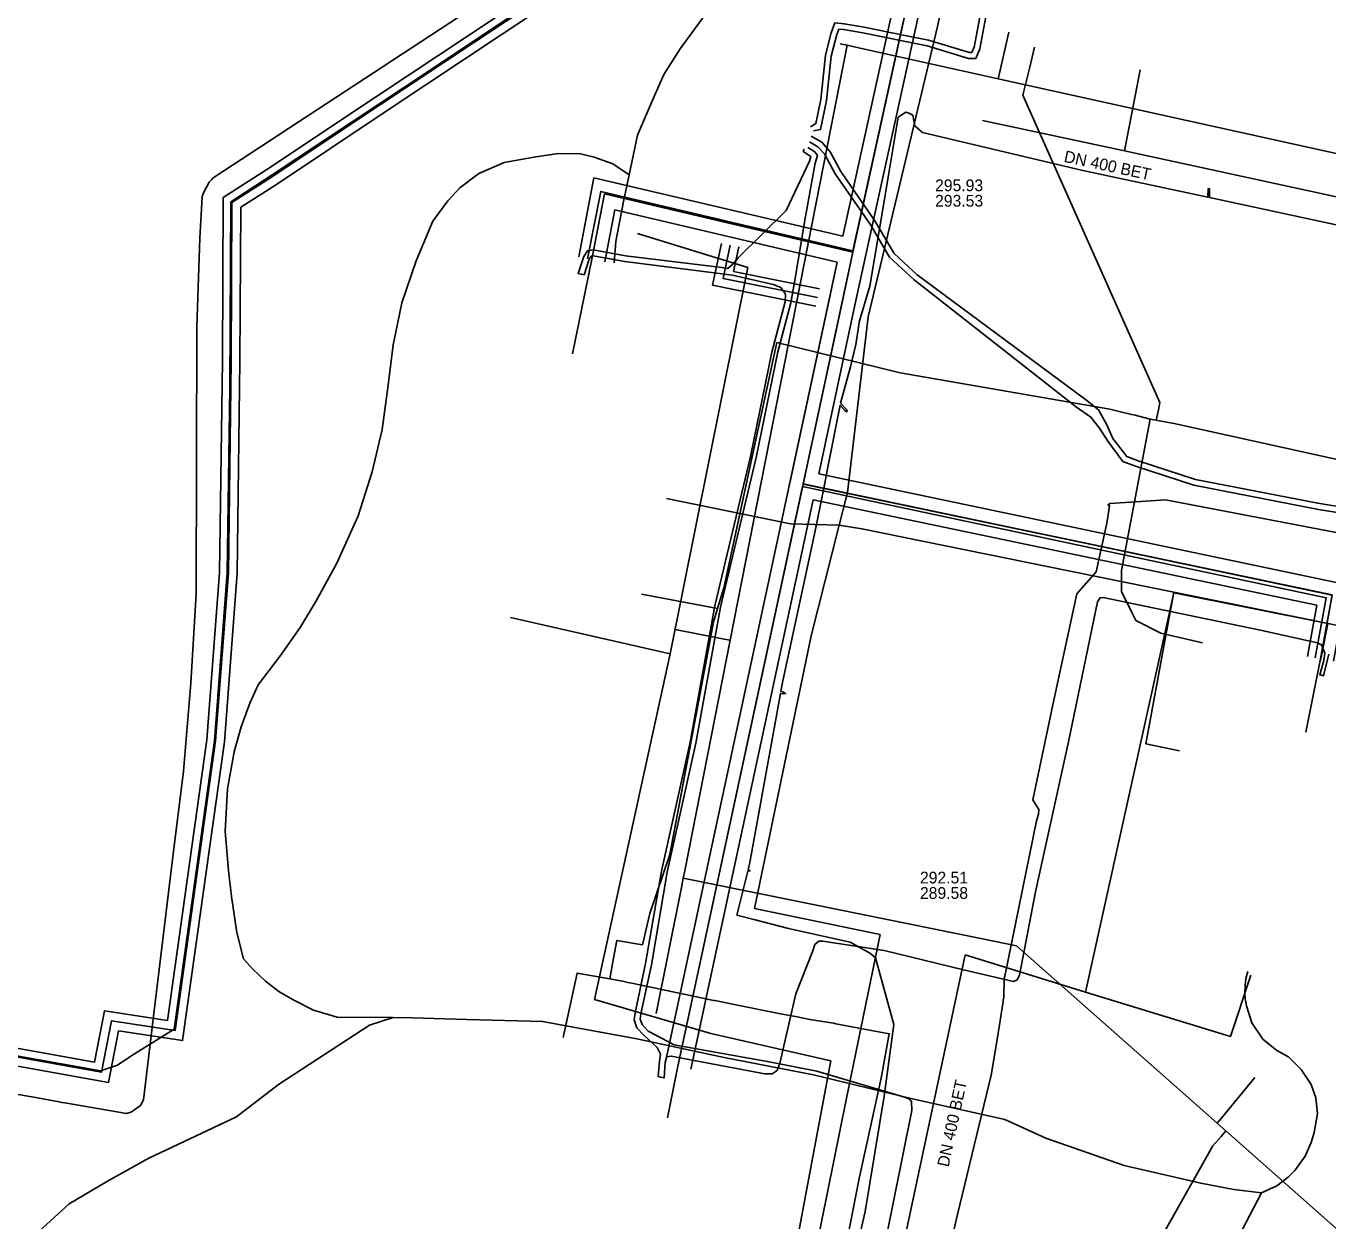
# Model space of a CAD drawing. Extents: x -598233 to -596890, y -1157848 to -1156431.
# Drawn here: x -597231.9 to -597143.3, y -1156744.9 to -1156663.6 of the extents above; entities that cross this region are included whole.
import ezdxf

# ---------------------------------------------------------------- set-up
doc = ezdxf.new("R2010")
doc.units = 0
for name, color, linetype in [('Vrstva 12', 7, 'Continuous'), ('Vrstva 13', 7, 'Continuous'), ('Vrstva 19', 7, 'Continuous'), ('Vrstva 25', 7, 'Continuous'), ('Vrstva 26', 7, 'Continuous'), ('Vrstva 37', 7, 'Continuous'), ('Vrstva 38', 7, 'Continuous'), ('Vrstva 42', 7, 'Continuous'), ('Vrstva 55', 7, 'Continuous'), ('Vrstva 58', 7, 'Continuous'), ('Vrstva 9', 7, 'Continuous')]:
    doc.layers.add(name, color=color, linetype=linetype)

msp = doc.modelspace()

# ---------------------------------------------------------------- linework, layer by layer
at = {"layer": 'Vrstva 12'}
for points in [[(-597150.87, -1156655.17), (-597167.31, -1156651.68), (-597167.95, -1156654.73), (-597169.84, -1156663.6), (-597174.56, -1156683.37), (-597175.97, -1156695.33)], [(-597176.54, -1156697.56), (-597179.87, -1156697.47), (-597188.3, -1156695.75)], [(-597175.97, -1156695.33), (-597176.54, -1156697.56)], [(-597176.54, -1156697.56), (-597178.46, -1156705.1), (-597182.31, -1156723.66), (-597173.76, -1156725.44), (-597176.06, -1156736.69), (-597180.66, -1156759.37), (-597193.75, -1156756.94), (-597193.48, -1156755.67)], [(-597176.54, -1156697.56), (-597175, -1156697.81), (-597162.26, -1156700.4), (-597153.76, -1156702.13)], [(-597153.38, -1156712.93), (-597155.66, -1156712.46), (-597153.76, -1156702.13)], [(-597153.76, -1156702.13), (-597151.31, -1156702.63), (-597149.84, -1156702.93)], [(-597149.84, -1156702.93), (-597135.23, -1156705.9), (-597127.25, -1156707.5)]]:
    msp.add_lwpolyline(points, dxfattribs=at)
at = {"layer": 'Vrstva 13'}
for p, q in [((-597175.996, -1156664.889), (-597176.471, -1156664.782)), ((-597175.517, -1156665.001), (-597175.996, -1156664.889)), ((-597150.546, -1156739.193), (-597150.21, -1156738.813))]:
    msp.add_line(p, q, dxfattribs=at)
for points in [[(-597247.46, -1156733.78), (-597231.39, -1156736.52), (-597229.65, -1156736.84), (-597229.47, -1156736.87), (-597229.272, -1156736.898), (-597225.07, -1156737.63), (-597224.849, -1156737.554), (-597224.69, -1156737.5), (-597224.09, -1156737.05), (-597223.994, -1156736.848), (-597223.92, -1156736.69), (-597223.11, -1156730.07), (-597222.66, -1156726.33), (-597221.93, -1156720.32), (-597221.18, -1156714.32), (-597220.68, -1156708.32), (-597220.32, -1156702.25), (-597220.28, -1156684.06), (-597220.08, -1156678.01), (-597219.92, -1156675.21), (-597219.863, -1156675.039), (-597219.81, -1156674.88), (-597219.43, -1156674.21), (-597219.289, -1156674.053), (-597219.16, -1156673.91), (-597195.36, -1156658.29)], [(-597165.716, -1156667.167), (-597165.627, -1156666.774), (-597164.999, -1156663.991)], [(-597175.996, -1156664.889), (-597183.97, -1156705.396), (-597187.061, -1156721.098)], [(-597084.22, -1156685.17), (-597106.726, -1156680.198), (-597165.716, -1156667.167), (-597175.517, -1156665.001)], [(-597183.97, -1156705.396), (-597184.366, -1156705.316), (-597187.706, -1156704.657)], [(-597187.157, -1156721.604), (-597187.288, -1156722.246), (-597188.999, -1156730.813)], [(-597187.061, -1156721.098), (-597187.157, -1156721.604), (-597186.716, -1156721.695)], [(-597186.716, -1156721.695), (-597166.776, -1156725.741), (-597164.475, -1156726.208), (-597150.803, -1156738.287), (-597150.21, -1156738.813)], [(-597150.803, -1156738.287), (-597150.646, -1156738.098), (-597148.235, -1156735.163)], [(-597174.453, -1156777.378), (-597172.482, -1156777.806), (-597151.095, -1156739.831), (-597150.546, -1156739.193)], [(-597150.21, -1156738.813), (-597130.738, -1156756.023), (-597129.302, -1156757.289), (-597024.857, -1156779.119), (-596949.21, -1156795.28)]]:
    msp.add_lwpolyline(points, dxfattribs=at)
at = {"layer": 'Vrstva 19'}
for points in [[(-597163.57, -1156666.37), (-597163.24, -1156665.01)], [(-597154.71, -1156689.2), (-597164.04, -1156668.28), (-597163.57, -1156666.37)], [(-597180.78, -1156685.12), (-597184.3, -1156701.42)], [(-597158.12, -1156689.66), (-597172.4, -1156687.19), (-597180.78, -1156685.12)], [(-597157.76, -1156689.75), (-597158.12, -1156689.66)], [(-597156.4, -1156690.08), (-597156.63, -1156690.03), (-597157.76, -1156689.75)], [(-597154.97, -1156690.41), (-597154.8, -1156689.71)], [(-597154.8, -1156689.71), (-597154.71, -1156689.2)], [(-597156.4, -1156690.08), (-597155.36, -1156690.34), (-597154.97, -1156690.41), (-597154.38, -1156690.52)], [(-597155.456, -1156690.831), (-597155.36, -1156690.34)], [(-597154.38, -1156690.52), (-597153.74, -1156690.63)], [(-597153.74, -1156690.63), (-597135.86, -1156694.59), (-597088.849, -1156704.811), (-597082.78, -1156706.13), (-597053.385, -1156713.142)], [(-597151.81, -1156705.57), (-597154.65, -1156704.91), (-597156.35, -1156704.06), (-597156.571, -1156703.611), (-597157.32, -1156702.09), (-597157.33, -1156700.65), (-597155.99, -1156693.56), (-597155.456, -1156690.831)], [(-597184.4, -1156701.83), (-597184.82, -1156703.23), (-597185.04, -1156703.95), (-597185.07, -1156704.05)], [(-597184.4, -1156701.83), (-597184.3, -1156701.42)], [(-597190, -1156702.27), (-597184.82, -1156703.23)], [(-597185.07, -1156704.05), (-597185.1, -1156704.16), (-597188.08, -1156719.99), (-597189.44, -1156724.01), (-597189.93, -1156726.14)], [(-597189.93, -1156726.14), (-597191.68, -1156725.84), (-597191.85, -1156726.68)], [(-597191.85, -1156726.68), (-597191.96, -1156727.29), (-597192.16, -1156728.45)], [(-597192.16, -1156728.45), (-597194.38, -1156728.06), (-597195.33, -1156732.45)], [(-597183.69, -1156730.21), (-597184.99, -1156729.94), (-597185.04, -1156729.93), (-597185.1, -1156729.92), (-597186.25, -1156729.68), (-597190.66, -1156728.76), (-597190.83, -1156728.72), (-597191.04, -1156728.68), (-597191.08, -1156728.67), (-597192.16, -1156728.45)], [(-597179.59, -1156774.8), (-597179.44, -1156774.13), (-597175.85, -1156755.06), (-597175.63, -1156753.94), (-597176.98, -1156751.44), (-597176.36, -1156748.1), (-597175.18, -1156742.06), (-597173.69, -1156735.22), (-597173.13, -1156732.2), (-597176.77, -1156731.51), (-597176.93, -1156731.48), (-597178.55, -1156731.22), (-597179.51, -1156731.03), (-597180.55, -1156730.83), (-597183.69, -1156730.21)]]:
    msp.add_lwpolyline(points, dxfattribs=at)
at = {"layer": 'Vrstva 25'}
msp.add_lwpolyline([(-597197.063, -1156661.799), (-597207.78, -1156668.921), (-597215.19, -1156673.858), (-597217.887, -1156675.59), (-597217.942, -1156686.39), (-597218.136, -1156700.806), (-597219.005, -1156712.256), (-597221.765, -1156731.976), (-597226.092, -1156731.323), (-597226.772, -1156734.815), (-597245.144, -1156731.523)], dxfattribs=at)
at = {"layer": 'Vrstva 26'}
for points in [[(-597245.036, -1156730.933), (-597227.248, -1156734.12), (-597226.571, -1156730.644), (-597222.275, -1156731.292), (-597219.602, -1156712.192), (-597218.736, -1156700.78), (-597218.542, -1156686.384), (-597218.485, -1156675.261), (-597215.519, -1156673.356), (-597208.113, -1156668.422), (-597197.397, -1156661.301)], [(-597196.728, -1156662.297), (-597207.448, -1156669.421), (-597214.862, -1156674.36), (-597217.288, -1156675.919), (-597217.342, -1156686.395), (-597217.537, -1156700.833), (-597218.408, -1156712.32), (-597221.255, -1156732.66), (-597225.613, -1156732.002), (-597226.296, -1156735.51), (-597245.252, -1156732.113)]]:
    msp.add_lwpolyline(points, dxfattribs=at)
at = {"layer": 'Vrstva 37'}
for p, q in [((-597179.003, -1156694.755), (-597175.614, -1156678.971)), ((-597193.385, -1156679.457), (-597194.691, -1156685.887)), ((-597179.006, -1156694.768), (-597187.52, -1156734.41)), ((-597179.049, -1156694.926), (-597187.52, -1156734.41)), ((-597143.773, -1156706.674), (-597144.77, -1156711.662)), ((-597187.52, -1156734.41), (-597188.236, -1156737.92))]:
    msp.add_line(p, q, dxfattribs=at)
for points in [[(-597163.153, -1156657.988), (-597170.684, -1156656.494), (-597175.614, -1156678.971)], [(-597175.607, -1156678.888), (-597170.684, -1156656.494), (-597163.153, -1156657.988)], [(-597175.607, -1156678.888), (-597192.778, -1156674.84), (-597193.675, -1156679.43)], [(-597175.614, -1156678.971), (-597183.677, -1156677.083), (-597192.534, -1156675.009), (-597193.385, -1156679.457)], [(-597175.614, -1156678.971), (-597192.534, -1156675.009), (-597193.385, -1156679.457)], [(-597178.013, -1156682.066), (-597184.448, -1156680.756), (-597183.974, -1156678.498)], [(-597175.614, -1156678.971), (-597176.351, -1156682.404), (-597179.006, -1156694.768)], [(-597179.049, -1156694.926), (-597143.379, -1156702.511), (-597144.136, -1156706.595)], [(-597179.006, -1156694.768), (-597142.983, -1156702.318), (-597143.773, -1156706.674)], [(-597143.773, -1156706.674), (-597142.983, -1156702.318), (-597179.003, -1156694.755)]]:
    msp.add_lwpolyline(points, dxfattribs=at)
at = {"layer": 'Vrstva 38'}
for p, q in [((-597176.679, -1156679.646), (-597188.4, -1156734.221)), ((-597178.314, -1156695.833), (-597186.64, -1156734.599))]:
    msp.add_line(p, q, dxfattribs=at)
for points in [[(-597176.298, -1156677.887), (-597171.374, -1156655.44), (-597162.978, -1156657.105)], [(-597163.328, -1156658.871), (-597169.994, -1156657.548), (-597174.735, -1156679.164)], [(-597194.269, -1156679.288), (-597193.242, -1156673.919), (-597183.472, -1156676.207), (-597176.298, -1156677.887)], [(-597176.679, -1156679.646), (-597191.826, -1156676.099), (-597192.501, -1156679.626)], [(-597178.133, -1156682.654), (-597185.159, -1156681.224), (-597184.561, -1156678.374)], [(-597183.387, -1156678.621), (-597183.737, -1156680.288), (-597177.894, -1156681.478)], [(-597179.886, -1156694.579), (-597177.231, -1156682.215), (-597176.679, -1156679.646)], [(-597174.734, -1156679.16), (-597175.471, -1156682.593), (-597177.936, -1156694.073)], [(-597177.936, -1156694.073), (-597141.941, -1156701.617), (-597142.887, -1156706.835)], [(-597144.659, -1156706.513), (-597144.025, -1156703.019), (-597178.314, -1156695.833)]]:
    msp.add_lwpolyline(points, dxfattribs=at)
at = {"layer": 'Vrstva 42'}
for p, q in [((-597179, -1156694.75), (-597175.61, -1156678.97)), ((-597179.05, -1156694.93), (-597187.52, -1156734.41))]:
    msp.add_line(p, q, dxfattribs=at)
for points in [[(-597178.486, -1156670.435), (-597178.131, -1156670.214), (-597177.798, -1156668.58), (-597177.487, -1156665.554), (-597177.081, -1156664.04), (-597176.835, -1156663.368), (-597176.195, -1156663.421), (-597174.853, -1156663.653), (-597171.951, -1156664.244), (-597170.462, -1156664.536), (-597167.677, -1156665.381), (-597167.513, -1156665.386), (-597167.363, -1156665.013), (-597166.675, -1156661.387), (-597165.865, -1156658.176), (-597165.205, -1156654.844), (-597164.932, -1156653.862), (-597163.927, -1156653.229), (-597162.117, -1156653.25), (-597160.156, -1156653.685), (-597157.342, -1156654.316), (-597151.872, -1156655.786), (-597141.913, -1156657.693)], [(-597152.723, -1156655.971), (-597157.438, -1156654.704), (-597160.244, -1156654.075), (-597162.163, -1156653.65), (-597163.813, -1156653.631), (-597164.588, -1156654.118), (-597164.815, -1156654.936), (-597165.475, -1156658.264), (-597166.285, -1156661.473), (-597166.977, -1156665.127), (-597167.247, -1156665.794), (-597167.743, -1156665.779), (-597170.558, -1156664.924), (-597172.029, -1156664.636), (-597174.927, -1156664.047), (-597176.245, -1156663.819), (-597176.565, -1156663.792), (-597176.699, -1156664.16), (-597177.093, -1156665.626), (-597177.402, -1156668.64), (-597177.807, -1156670.625), (-597178.294, -1156670.72)], [(-597175.61, -1156678.89), (-597170.68, -1156656.49), (-597163.15, -1156657.99)], [(-597198.61, -1156662.73), (-597206.14, -1156667.74), (-597215.21, -1156673.75), (-597217.96, -1156675.54), (-597218.04, -1156688.17), (-597218.22, -1156700.81), (-597219.08, -1156712.24), (-597221.83, -1156731.89), (-597224.71, -1156733.67), (-597225.68, -1156734.34), (-597226.83, -1156734.72), (-597243.23, -1156731.79)], [(-597137.354, -1156697.145), (-597143.964, -1156696.072), (-597152.281, -1156694.455), (-597156.178, -1156693.194), (-597156.967, -1156692.893), (-597157.902, -1156691.663), (-597158.309, -1156690.738), (-597158.894, -1156689.7), (-597159.77, -1156689.003), (-597171.236, -1156680.51), (-597172.799, -1156679.054), (-597174.109, -1156676.846), (-597176.441, -1156673.476), (-597177.165, -1156672.131), (-597177.729, -1156671.488), (-597178.446, -1156671.066)], [(-597178.937, -1156671.966), (-597178.986, -1156672.127), (-597178.6, -1156672.365), (-597178.474, -1156672.455), (-597178.561, -1156672.783), (-597180.15, -1156676.144), (-597183.424, -1156679.358), (-597183.774, -1156679.791), (-597184.115, -1156680.093), (-597184.545, -1156680.012), (-597191.085, -1156679.215), (-597193.294, -1156678.811), (-597193.673, -1156678.874), (-597193.935, -1156679.27), (-597194.318, -1156680.423), (-597194.112, -1156680.466), (-597193.911, -1156680.513), (-597193.571, -1156679.446), (-597193.435, -1156679.24), (-597193.298, -1156679.217), (-597191.145, -1156679.611), (-597183.806, -1156680.547), (-597181.041, -1156681.17), (-597180.52, -1156681.389), (-597180.207, -1156681.827), (-597180.23, -1156682.362), (-597181.126, -1156685.788), (-597182.591, -1156692.88), (-597185.006, -1156703.063), (-597186.69, -1156712.337), (-597188.651, -1156721.12), (-597189.726, -1156727.418), (-597190.442, -1156730.772), (-597190.503, -1156731.24), (-597190.318, -1156731.783), (-597189.837, -1156732.288), (-597188.936, -1156733.131), (-597188.703, -1156733.592), (-597188.781, -1156734.071), (-597188.871, -1156735.105), (-597188.701, -1156735.147), (-597188.47, -1156735.204), (-597188.383, -1156734.125), (-597188.31, -1156733.766), (-597187.975, -1156733.713), (-597181.609, -1156734.929), (-597181.111, -1156734.928), (-597180.772, -1156734.691), (-597180.598, -1156734.244), (-597180.582, -1156734.203), (-597179.505, -1156729.477), (-597178.346, -1156726.554), (-597178.207, -1156726.119), (-597177.933, -1156725.884), (-597177.654, -1156725.894), (-597173.472, -1156726.535), (-597168.085, -1156727.852), (-597164.675, -1156728.642), (-597164.424, -1156728.523), (-597164.257, -1156728.207), (-597163.174, -1156722.527), (-597160.92, -1156712.322), (-597158.958, -1156702.777), (-597158.776, -1156702.504), (-597158.578, -1156702.491), (-597147.972, -1156704.682), (-597143.987, -1156705.581), (-597143.698, -1156705.717), (-597143.483, -1156706.278), (-597143.553, -1156706.768), (-597143.821, -1156707.758), (-597143.697, -1156707.789), (-597143.572, -1156707.82), (-597143.338, -1156706.891), (-597143.199, -1156706.354)], [(-597173.9, -1156748.787), (-597171.589, -1156737.415), (-597171.618, -1156736.803), (-597171.779, -1156736.621), (-597172.098, -1156736.515), (-597178.064, -1156734.732), (-597180.598, -1156734.244), (-597181.437, -1156734.083), (-597187.79, -1156732.949), (-597189.547, -1156732.012), (-597189.968, -1156731.571), (-597190.095, -1156731.2), (-597190.048, -1156730.84), (-597189.334, -1156727.494), (-597188.259, -1156721.198), (-597186.298, -1156712.417), (-597184.614, -1156703.145), (-597182.201, -1156692.966), (-597180.726, -1156685.759), (-597179.834, -1156682.428), (-597179.51, -1156680.624), (-597178.88, -1156676.805), (-597178.179, -1156672.907), (-597178.028, -1156672.385), (-597178.196, -1156672.147), (-597178.688, -1156671.841)], [(-597178.567, -1156671.451), (-597177.987, -1156671.8), (-597177.536, -1156672.271), (-597176.816, -1156673.632), (-597174.445, -1156677.062), (-597173.113, -1156679.308), (-597171.448, -1156680.86), (-597160.377, -1156689.528), (-597159.409, -1156690.209), (-597158.821, -1156690.954), (-597158.259, -1156691.853), (-597157.241, -1156693.221), (-597156.366, -1156693.549), (-597152.394, -1156694.847), (-597143.915, -1156696.486), (-597137.408, -1156697.549)], [(-597175.61, -1156678.89), (-597192.78, -1156674.84), (-597193.68, -1156679.43)], [(-597175.61, -1156678.97), (-597192.53, -1156675.01), (-597193.39, -1156679.46)], [(-597179.05, -1156694.93), (-597143.38, -1156702.51), (-597144.14, -1156706.59)], [(-597143.77, -1156706.67), (-597142.98, -1156702.32), (-597179, -1156694.75)]]:
    msp.add_lwpolyline(points, dxfattribs=at)
at = {"layer": 'Vrstva 55'}
for points in [[(-597171.859, -1156669.488), (-597172.01, -1156669.45), (-597172.53, -1156669.79), (-597173.485, -1156675.504), (-597174.45, -1156681.28), (-597175.15, -1156683.66), (-597175.4, -1156685.26), (-597175.77, -1156686.78), (-597176.451, -1156689.251), (-597176.053, -1156689.698), (-597176.007, -1156689.841), (-597176.135, -1156689.787), (-597176.484, -1156689.394), (-597177.33, -1156693.725), (-597177.52, -1156694.7), (-597178.2, -1156698.06), (-597179.906, -1156705.963), (-597180.38, -1156708.16), (-597180.513, -1156708.898), (-597180.325, -1156708.942), (-597180.19, -1156709.035), (-597180.352, -1156709.059), (-597180.535, -1156709.016), (-597181.014, -1156711.664), (-597182.62, -1156720.54), (-597182.735, -1156721.001), (-597182.61, -1156721.11), (-597182.764, -1156721.118), (-597183.51, -1156724.11), (-597182.258, -1156724.438), (-597180, -1156725.03), (-597175.79, -1156725.95), (-597174.42, -1156726.73), (-597174.07, -1156727.03), (-597172.83, -1156731.56), (-597173.48, -1156736.45), (-597174.77, -1156744.29), (-597175.8, -1156748.76)], [(-597098.689, -1156686.62), (-597105.78, -1156685.13), (-597116.381, -1156682.831), (-597116.21, -1156682.298), (-597116.26, -1156682.14), (-597116.479, -1156682.809), (-597124.05, -1156681.15), (-597133.821, -1156679.11), (-597133.699, -1156678.204), (-597133.95, -1156678.35), (-597133.821, -1156678.356), (-597133.919, -1156679.089), (-597141.23, -1156677.42), (-597151.34, -1156675.241), (-597151.32, -1156674.652), (-597151.42, -1156674.648), (-597151.44, -1156675.219), (-597159.95, -1156673.41), (-597170.87, -1156670.82), (-597171.4, -1156670.38), (-597171.532, -1156669.634), (-597171.857, -1156669.49)], [(-597142.339, -1156698.129), (-597154.33, -1156695.84), (-597157.05, -1156696.02), (-597158.12, -1156696.09), (-597158.25, -1156696.2), (-597158.144, -1156696.243), (-597158.33, -1156697.43), (-597159.05, -1156700.74), (-597160.37, -1156702.25), (-597161.987, -1156709.801), (-597163.37, -1156716.26), (-597162.94, -1156716.93), (-597162.97, -1156717.25), (-597163.12, -1156717.7), (-597165.265, -1156728.268), (-597165.3, -1156728.44), (-597165.34, -1156729.77), (-597165.38, -1156729.858), (-597165.38, -1156730.01), (-597165.77, -1156732.46), (-597166.19, -1156735.02), (-597168.479, -1156744.507), (-597168.9, -1156746.25)]]:
    msp.add_lwpolyline(points, dxfattribs=at)
at = {"layer": 'Vrstva 58'}
for points in [[(-597190.84, -1156673.7), (-597190.28, -1156671.009), (-597189.47, -1156669.09), (-597188.481, -1156666.88), (-597187.38, -1156665.12), (-597185.903, -1156663.099), (-597184.32, -1156661.18), (-597182.426, -1156659.319), (-597180.6, -1156658.06), (-597178.888, -1156657.341), (-597177.18, -1156656.94), (-597173.951, -1156657.167), (-597170.713, -1156657.574), (-597168.35, -1156657.96), (-597166.21, -1156658.44), (-597164.957, -1156658.709), (-597163.48, -1156658.8)], [(-597206.92, -1156731.08), (-597210.72, -1156731.07), (-597212.335, -1156730.588), (-597213.684, -1156729.919), (-597214.69, -1156729.31), (-597215.602, -1156728.61), (-597216.472, -1156727.796), (-597217.1, -1156727.09), (-597217.56, -1156725.29), (-597217.92, -1156722.84), (-597218.12, -1156721.07), (-597218.35, -1156718.425), (-597218.2, -1156715.517), (-597217.75, -1156712.987), (-597217.273, -1156711.286), (-597216.674, -1156709.687), (-597216.11, -1156708.43), (-597214.575, -1156706.43), (-597213.256, -1156704.539), (-597212.17, -1156702.77), (-597210.74, -1156700.14), (-597209.306, -1156696.937), (-597208.346, -1156693.942), (-597207.66, -1156691.05), (-597207.26, -1156688.02), (-597206.911, -1156685.274), (-597206.312, -1156682.424), (-597205.352, -1156679.574), (-597204.22, -1156676.86), (-597203.195, -1156675.484), (-597202.38, -1156674.59), (-597201.072, -1156673.627), (-597199.363, -1156672.871), (-597197.2, -1156672.48), (-597195.646, -1156672.26), (-597194.147, -1156672.289), (-597193.23, -1156672.5), (-597191.959, -1156672.958), (-597190.84, -1156673.7)], [(-597190.84, -1156673.7), (-597191.239, -1156675.517), (-597191.749, -1156678.251), (-597191.87, -1156679.69)], [(-597147.8, -1156743.02), (-597146.735, -1156742.56), (-597145.971, -1156741.964), (-597145.51, -1156741.51), (-597144.816, -1156740.54), (-597144.397, -1156739.609), (-597144.2, -1156738.91), (-597143.977, -1156737.632), (-597144.097, -1156736.556), (-597144.4, -1156735.66), (-597145.086, -1156734.621), (-597145.955, -1156733.777), (-597146.74, -1156733.33), (-597147.693, -1156732.556), (-597148.443, -1156731.451), (-597148.802, -1156730.288), (-597148.9, -1156729.82), (-597148.92, -1156729.46), (-597148.912, -1156728.904), (-597148.852, -1156728.427), (-597148.73, -1156727.95)], [(-597206.92, -1156731.08), (-597208.53, -1156731.6), (-597214.71, -1156735.64), (-597217.58, -1156737.85), (-597223.55, -1156740.66), (-597226.36, -1156742.23), (-597228.97, -1156743.78), (-597234.63, -1156748.91), (-597238.67, -1156754.43), (-597246.37, -1156761.26), (-597247.93, -1156763.67), (-597250.14, -1156766.32), (-597253.5, -1156769.67), (-597254.16, -1156769.87), (-597257.84, -1156776.46), (-597258.33, -1156779.41), (-597259.81, -1156783.2), (-597260.62, -1156783.96), (-597262.04, -1156787.09), (-597262.83, -1156788.54), (-597263.2, -1156790.21)], [(-597147.8, -1156743.02), (-597149.668, -1156742.794), (-597151.93, -1156742.37), (-597157.147, -1156741.166), (-597162.483, -1156739.305), (-597165.27, -1156738.03), (-597171.55, -1156736.62), (-597178.3, -1156735), (-597184.37, -1156733.82), (-597190.32, -1156732.53), (-597196.74, -1156731.36), (-597201.886, -1156731.227), (-597205.61, -1156731.1), (-597206.92, -1156731.08)], [(-597170.79, -1156805.39), (-597170.961, -1156805.029), (-597170.92, -1156804.67), (-597167.7, -1156789.04), (-597165.46, -1156781.58), (-597165.05, -1156780.53), (-597163.73, -1156775.29), (-597163.61, -1156773.85), (-597164.25, -1156768.77), (-597164.22, -1156767.15), (-597161.85, -1156762.64), (-597157.89, -1156756.6), (-597154.25, -1156752.02), (-597153.19, -1156749.9), (-597149.64, -1156746.6), (-597147.8, -1156743.02)]]:
    msp.add_lwpolyline(points, dxfattribs=at)
at = {"layer": 'Vrstva 9'}
for p, q in [((-597156.048, -1156666.562), (-597156.49, -1156668.812)), ((-597156.49, -1156668.812), (-597157.115, -1156672.085)), ((-597190.278, -1156677.708), (-597182.757, -1156680.025)), ((-597182.757, -1156680.025), (-597188.062, -1156706.324)), ((-597153.762, -1156702.16), (-597159.766, -1156729.359)), ((-597143.276, -1156704.252), (-597153.762, -1156702.16)), ((-597198.926, -1156703.844), (-597188.062, -1156706.324)), ((-597143.768, -1156706.776), (-597143.276, -1156704.252)), ((-597188.062, -1156706.324), (-597193.198, -1156729.858)), ((-597167.968, -1156726.832), (-597172.744, -1156749.23)), ((-597148.517, -1156728.214), (-597149.908, -1156732.39)), ((-597193.198, -1156729.858), (-597185.284, -1156732.177)), ((-597185.284, -1156732.177), (-597177.102, -1156734.032)), ((-597177.102, -1156734.032), (-597179.526, -1156746.866))]:
    msp.add_line(p, q, dxfattribs=at)
for points in [[(-597166.776, -1156670.012), (-597157.115, -1156672.085), (-597139.354, -1156675.933), (-597136.227, -1156676.603), (-597132.189, -1156677.468)], [(-597149.908, -1156732.39), (-597159.766, -1156729.359), (-597167.968, -1156726.832)]]:
    msp.add_lwpolyline(points, dxfattribs=at)

# ---------------------------------------------------------------- texts
at = {"layer": 'Vrstva 12'}
for rotation, p in [(347.84268, (-597161.288, -1156672.819)), (77.96291, (-597169.094, -1156741.312))]:
    msp.add_text('DN 400 BET', height=0.8, rotation=rotation, dxfattribs=at).set_placement(p)
for s, p in [('295.93', (-597170.014, -1156674.822)), ('293.53', (-597170.014, -1156675.872)), ('292.51', (-597171.043, -1156721.96)), ('289.58', (-597171.043, -1156723.01))]:
    msp.add_text(s, height=0.8, dxfattribs=at).set_placement(p)

doc.saveas('drawing.dxf')
